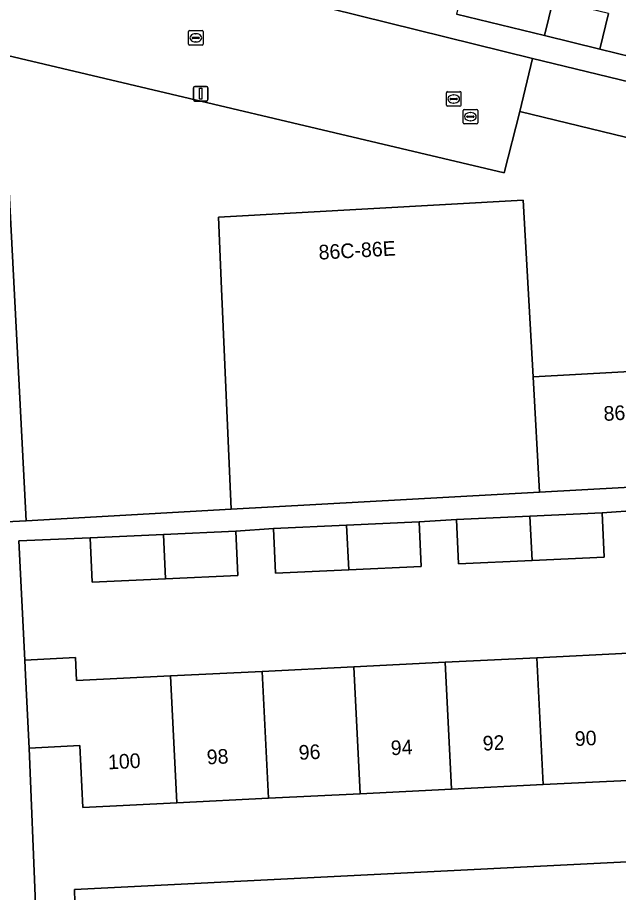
# Model space of a CAD drawing. Extents: x 161084 to 161928, y 385354 to 386522.
# Drawn here: x 161376.6 to 161417.7, y 385753.3 to 385813.1 of the extents above; entities that cross this region are included whole.
import ezdxf

# ---------------------------------------------------------------- set-up
doc = ezdxf.new("R2010")
doc.units = 0
for name, color, linetype in [('IMGEO_Erf', 7, 'Continuous'), ('IMGEO_Kolk', 7, 'Continuous'), ('IMGEO_Lichtmast', 7, 'Continuous'), ('IMGEO_Pand', 7, 'Continuous'), ('IMGEO_Pand_nummerreeks', 7, 'Continuous'), ('IMGEO_Rijbaan_lokaal_open', 7, 'Continuous'), ('IMGEO_Rioolput', 7, 'Continuous'), ('IMGEO_Voetpad_open', 7, 'Continuous')]:
    doc.layers.add(name, color=color, linetype=linetype)

msp = doc.modelspace()

# ---------------------------------------------------------------- linework, layer by layer
at = {"layer": 'IMGEO_Erf'}
for points in [[(161416.978, 385813.418), (161416.393, 385810.987), (161418.627, 385810.445)], [(161419.122, 385779.431), (161416.549, 385779.256), (161416.686, 385776.213), (161411.751, 385775.99), (161406.729, 385775.763), (161406.592, 385778.806), (161404.022, 385778.631), (161404.159, 385775.588), (161399.223, 385775.365), (161394.202, 385775.138), (161394.065, 385778.181), (161391.493, 385778.006), (161391.63, 385774.963), (161386.693, 385774.74), (161381.673, 385774.513), (161381.536, 385777.556), (161376.653, 385777.335), (161377.063, 385769.185), (161380.524, 385769.358), (161380.603, 385767.775), (161387.025, 385768.095), (161393.289, 385768.407), (161399.554, 385768.72), (161405.818, 385769.032), (161412.082, 385769.345), (161418.347, 385769.658)]]:
    msp.add_lwpolyline(points, dxfattribs=at)
for points in [[(161419.725, 385800.816), (161420.585, 385804.362), (161410.905, 385806.71), (161409.837, 385802.513), (161375.498, 385810.645), (161375.758, 385805.652), (161377.159, 385778.718), (161391.177, 385779.498), (161390.518, 385794.589), (161390.305, 385799.48), (161411.15, 385800.639), (161411.822, 385788.558), (161423.814, 385789.225), (161423.702, 385791.242), (161438.972, 385792.091), (161438.748, 385796.202), (161438.45, 385801.656), (161438.985, 385803.861), (161433.66, 385805.153), (161431.893, 385797.865)], [(161453.458, 385766.91), (161450.05, 385766.74), (161450.26, 385762.549), (161443.836, 385762.228), (161437.572, 385761.916), (161431.308, 385761.603), (161425.044, 385761.29), (161418.78, 385760.978), (161412.515, 385760.665), (161406.251, 385760.353), (161399.987, 385760.04), (161393.723, 385759.727), (161387.459, 385759.415), (161381.035, 385759.094), (161380.824, 385763.331), (161377.364, 385763.158), (161377.787, 385752.478), (161380.483, 385752.611), (161380.46, 385753.49), (161418.265, 385755.389), (161453.943, 385757.182)]]:
    msp.add_lwpolyline(points, close=True, dxfattribs=at)
at = {"layer": 'IMGEO_Kolk'}
for p, q in [((161388.256, 385811.33), (161388.256, 385812.182)), ((161388.331, 385812.256), (161389.183, 385812.256)), ((161388.744, 385812.036), (161388.769, 385812.036)), ((161389.257, 385812.182), (161389.257, 385811.33)), ((161388.515, 385811.75), (161388.515, 385811.762)), ((161388.953, 385811.713), (161388.555, 385811.713)), ((161388.558, 385811.799), (161388.956, 385811.799)), ((161388.767, 385811.476), (161388.742, 385811.476)), ((161388.999, 385811.762), (161388.999, 385811.75)), ((161389.183, 385811.256), (161388.331, 385811.256)), ((161405.891, 385807.147), (161405.891, 385807.999)), ((161405.966, 385808.073), (161406.818, 385808.073)), ((161406.379, 385807.853), (161406.404, 385807.853)), ((161406.892, 385807.999), (161406.892, 385807.147)), ((161406.15, 385807.567), (161406.15, 385807.579)), ((161406.588, 385807.53), (161406.19, 385807.53)), ((161406.193, 385807.616), (161406.591, 385807.616)), ((161406.402, 385807.293), (161406.377, 385807.293)), ((161406.634, 385807.579), (161406.634, 385807.567)), ((161406.818, 385807.073), (161405.966, 385807.073))]:
    msp.add_line(p, q, dxfattribs=at)
for points in [[(161388.256, 385811.33), (161388.256, 385812.182)], [(161388.331, 385812.256), (161389.183, 385812.256)], [(161389.257, 385812.182), (161389.257, 385811.33)], [(161389.183, 385811.256), (161388.331, 385811.256)], [(161405.891, 385807.147), (161405.891, 385807.999)], [(161405.966, 385808.073), (161406.818, 385808.073)], [(161406.892, 385807.999), (161406.892, 385807.147)], [(161406.818, 385807.073), (161405.966, 385807.073)]]:
    msp.add_lwpolyline(points, dxfattribs=at)
for centre, radius, start, end in [((161388.333, 385812.18), 0.0765, 91.55205, 178.44795), ((161388.333, 385812.18), 0.0765, 91.55205, 178.44795), ((161389.181, 385812.18), 0.0765, 1.55205, 88.44795), ((161389.181, 385812.18), 0.0765, 1.55205, 88.44795), ((161388.333, 385811.332), 0.0765, 181.55205, 268.44795), ((161388.333, 385811.332), 0.0765, 181.55205, 268.44795), ((161388.555, 385811.759), 0.0403, 85.87752, 175.75265), ((161388.552, 385811.749), 0.0366, 178.93798, 274.71019), ((161388.956, 385811.756), 0.043, 264.86636, 352.45326), ((161388.96, 385811.761), 0.0386, 1.73085, 96.63898), ((161389.181, 385811.332), 0.0765, 271.55205, 358.44795), ((161389.181, 385811.332), 0.0765, 271.55205, 358.44795), ((161405.968, 385807.997), 0.0765, 91.55205, 178.44795), ((161405.968, 385807.997), 0.0765, 91.55205, 178.44795), ((161406.816, 385807.997), 0.0765, 1.55205, 88.44795), ((161406.816, 385807.997), 0.0765, 1.55205, 88.44795), ((161405.968, 385807.149), 0.0765, 181.55205, 268.44795), ((161405.968, 385807.149), 0.0765, 181.55205, 268.44795), ((161406.19, 385807.576), 0.0403, 85.87752, 175.75265), ((161406.187, 385807.566), 0.0366, 178.93798, 274.71019), ((161406.591, 385807.573), 0.043, 264.86636, 352.45326), ((161406.595, 385807.578), 0.0386, 1.73085, 96.63898), ((161406.816, 385807.149), 0.0765, 271.55205, 358.44795), ((161406.816, 385807.149), 0.0765, 271.55205, 358.44795)]:
    msp.add_arc(centre, radius, start, end, dxfattribs=at)
for centre, major_axis, ratio, start_param, end_param in [((161388.743, 385811.756), (-0.387, 0.002), 0.722429, 4.712389, 7.853982), ((161388.768, 385811.756), (-0.39, 0.002), 0.717154, 1.570796, 4.712389), ((161406.378, 385807.573), (-0.387, 0.002), 0.722429, 4.712389, 7.853982), ((161406.403, 385807.573), (-0.39, 0.002), 0.717154, 1.570796, 4.712389)]:
    msp.add_ellipse(centre, major_axis=major_axis, ratio=ratio, start_param=start_param, end_param=end_param, dxfattribs=at)
at = {"layer": 'IMGEO_Lichtmast'}
for p, q in [((161388.592, 385807.532), (161388.592, 385808.332)), ((161388.592, 385808.332), (161388.592, 385807.532)), ((161388.692, 385808.432), (161389.482, 385808.432)), ((161389.482, 385808.432), (161388.692, 385808.432)), ((161389.582, 385808.332), (161389.582, 385807.532)), ((161389.582, 385807.532), (161389.582, 385808.332)), ((161389.482, 385807.432), (161388.692, 385807.432)), ((161388.692, 385807.432), (161389.482, 385807.432))]:
    msp.add_line(p, q, dxfattribs=at)
msp.add_lwpolyline([(161389.012, 385808.307), (161389.162, 385808.307), (161389.162, 385807.557), (161389.012, 385807.557), (161389.012, 385808.307)], dxfattribs=at)
for centre, start, end in [((161388.692, 385808.332), 90, 180), ((161388.692, 385808.332), 90, 180), ((161389.482, 385808.332), 0, 90), ((161389.482, 385808.332), 360, 90), ((161388.692, 385807.532), 180, 270), ((161388.692, 385807.532), 180, 270), ((161389.482, 385807.532), 270, 0), ((161389.482, 385807.532), 270, 0)]:
    msp.add_arc(centre, 0.1, start, end, dxfattribs=at)
at = {"layer": 'IMGEO_Pand'}
for points in [[(161413.188, 385814.337), (161413.949, 385817.497), (161407.923, 385818.958), (161406.578, 385813.367), (161412.603, 385811.906)], [(161413.188, 385814.337), (161412.603, 385811.906), (161416.393, 385810.987), (161416.978, 385813.418)], [(161355.789, 385809.619), (161355.61, 385809.61), (161357.219, 385777.711), (161377.159, 385778.718), (161375.758, 385805.652), (161375.498, 385810.645)], [(161433.66, 385805.153), (161421.492, 385808.104), (161421.464, 385807.987), (161411.784, 385810.335), (161410.905, 385806.71), (161420.585, 385804.362), (161419.725, 385800.816), (161431.893, 385797.865)], [(161411.822, 385788.558), (161411.15, 385800.639), (161390.305, 385799.48), (161390.518, 385794.589), (161391.177, 385779.498), (161412.26, 385780.67)], [(161423.814, 385789.225), (161411.822, 385788.558), (161412.26, 385780.67), (161424.252, 385781.336)], [(161406.592, 385778.806), (161406.729, 385775.763), (161411.751, 385775.99), (161411.599, 385779.033)], [(161416.686, 385776.213), (161416.549, 385779.256), (161411.599, 385779.033), (161411.751, 385775.99)], [(161394.065, 385778.181), (161394.202, 385775.138), (161399.223, 385775.365), (161399.071, 385778.408)], [(161404.159, 385775.588), (161404.022, 385778.631), (161399.071, 385778.408), (161399.223, 385775.365)], [(161386.693, 385774.74), (161386.541, 385777.783), (161381.536, 385777.556), (161381.673, 385774.513)], [(161386.541, 385777.783), (161386.693, 385774.74), (161391.63, 385774.963), (161391.493, 385778.006)], [(161412.515, 385760.665), (161418.78, 385760.978), (161418.347, 385769.658), (161412.082, 385769.345)], [(161387.025, 385768.095), (161380.603, 385767.775), (161380.524, 385769.358), (161377.063, 385769.185), (161377.115, 385768.152), (161377.364, 385763.158), (161380.824, 385763.331), (161381.035, 385759.094), (161387.459, 385759.415)], [(161405.818, 385769.032), (161399.554, 385768.72), (161399.987, 385760.04), (161406.251, 385760.353)], [(161412.082, 385769.345), (161405.818, 385769.032), (161406.251, 385760.353), (161412.515, 385760.665)], [(161393.289, 385768.407), (161387.025, 385768.095), (161387.459, 385759.415), (161393.723, 385759.727)], [(161393.723, 385759.727), (161399.987, 385760.04), (161399.554, 385768.72), (161393.289, 385768.407)]]:
    msp.add_lwpolyline(points, close=True, dxfattribs=at)
at = {"layer": 'IMGEO_Rijbaan_lokaal_open'}
msp.add_lwpolyline([(161327.257, 385776.578), (161337.206, 385776.693), (161335.232, 385814.645), (161355.473, 385815.698), (161355.789, 385809.619), (161375.498, 385810.645), (161409.837, 385802.513), (161410.905, 385806.71), (161411.784, 385810.335), (161380.136, 385818.183)], dxfattribs=at)
at = {"layer": 'IMGEO_Rioolput'}
for p, q in [((161407.034, 385805.937), (161407.034, 385806.789)), ((161407.109, 385806.863), (161407.961, 385806.863)), ((161407.522, 385806.643), (161407.547, 385806.643)), ((161408.035, 385806.789), (161408.035, 385805.937)), ((161407.293, 385806.357), (161407.293, 385806.369)), ((161407.731, 385806.32), (161407.333, 385806.32)), ((161407.336, 385806.406), (161407.734, 385806.406)), ((161407.545, 385806.083), (161407.52, 385806.083)), ((161407.777, 385806.369), (161407.777, 385806.357)), ((161407.961, 385805.863), (161407.109, 385805.863))]:
    msp.add_line(p, q, dxfattribs=at)
for points in [[(161407.034, 385805.937), (161407.034, 385806.789)], [(161407.109, 385806.863), (161407.961, 385806.863)], [(161408.035, 385806.789), (161408.035, 385805.937)], [(161407.961, 385805.863), (161407.109, 385805.863)]]:
    msp.add_lwpolyline(points, dxfattribs=at)
for centre, radius, start, end in [((161407.111, 385806.787), 0.0765, 91.55205, 178.44795), ((161407.111, 385806.787), 0.0765, 91.55205, 178.44795), ((161407.959, 385806.787), 0.0765, 1.55205, 88.44795), ((161407.959, 385806.787), 0.0765, 1.55205, 88.44795), ((161407.111, 385805.939), 0.0765, 181.55205, 268.44795), ((161407.111, 385805.939), 0.0765, 181.55205, 268.44795), ((161407.333, 385806.366), 0.0403, 85.87752, 175.75265), ((161407.33, 385806.356), 0.0366, 178.93798, 274.71019), ((161407.734, 385806.363), 0.043, 264.86636, 352.45326), ((161407.738, 385806.368), 0.0386, 1.73085, 96.63898), ((161407.959, 385805.939), 0.0765, 271.55205, 358.44795), ((161407.959, 385805.939), 0.0765, 271.55205, 358.44795)]:
    msp.add_arc(centre, radius, start, end, dxfattribs=at)
for centre, major_axis, ratio, start_param, end_param in [((161407.521, 385806.363), (-0.387, 0.002), 0.722429, 4.712389, 7.853982), ((161407.546, 385806.363), (-0.39, 0.002), 0.717154, 1.570796, 4.712389)]:
    msp.add_ellipse(centre, major_axis=major_axis, ratio=ratio, start_param=start_param, end_param=end_param, dxfattribs=at)
at = {"layer": 'IMGEO_Voetpad_open'}
for points in [[(161380.136, 385818.183), (161411.784, 385810.335), (161421.464, 385807.987), (161421.492, 385808.104), (161433.66, 385805.153), (161438.985, 385803.861), (161462.196, 385798.233), (161465.837, 385811.74), (161465.969, 385812.301), (161467.677, 385819.591)], [(161464.399, 385814.367), (161463.657, 385811.285), (161461.568, 385802.604), (161460.983, 385800.173), (161458.664, 385800.736), (161454.779, 385801.678), (161452.526, 385802.224), (161448.754, 385803.139), (161446.495, 385803.687), (161442.727, 385804.6), (161436.703, 385806.061), (161434.414, 385806.616), (161430.677, 385807.522), (161424.652, 385808.984), (161422.434, 385809.522), (161418.627, 385810.445), (161416.393, 385810.987), (161412.603, 385811.906), (161406.578, 385813.367)], [(161424.252, 385781.336), (161412.26, 385780.67), (161391.177, 385779.498), (161377.159, 385778.718), (161357.219, 385777.711)], [(161377.787, 385752.478), (161377.364, 385763.158), (161377.115, 385768.152), (161377.063, 385769.185), (161376.653, 385777.335), (161381.536, 385777.556), (161386.541, 385777.783), (161391.493, 385778.006), (161394.065, 385778.181), (161399.071, 385778.408), (161404.022, 385778.631), (161406.592, 385778.806), (161411.599, 385779.033), (161416.549, 385779.256), (161419.122, 385779.431)], [(161534.012, 385757.077), (161559.087, 385758.539), (161575.415, 385759.247), (161583.446, 385759.696), (161587.221, 385759.881), (161588.617, 385759.949), (161588.602, 385760.241), (161588.85, 385760.254), (161588.705, 385762.992), (161588.446, 385762.979), (161586.836, 385762.898), (161533.843, 385760.213), (161533.793, 385761.193), (161532.383, 385761.122), (161500, 385759.495), (161455.526, 385757.261), (161454.823, 385757.226), (161453.943, 385757.182), (161418.265, 385755.389), (161380.46, 385753.49), (161380.483, 385752.611)]]:
    msp.add_lwpolyline(points, dxfattribs=at)

# ---------------------------------------------------------------- texts
at = {"layer": 'IMGEO_Pand_nummerreeks'}
for s, rotation, p in [('86C-86E', 3.18242, (161397.181, 385796.578)), ('86F', 3.18354, (161416.668, 385785.542)), ('92', 2.85724, (161408.401, 385762.983)), ('90', 2.85724, (161414.7, 385763.297)), ('96', 2.85724, (161395.817, 385762.355)), ('94', 2.85724, (161402.111, 385762.669)), ('100', 2.85906, (161382.774, 385761.703)), ('98', 2.85724, (161389.527, 385762.041))]:
    msp.add_text(s, height=1, rotation=rotation, dxfattribs=at).set_placement(p)

doc.saveas('drawing.dxf')
